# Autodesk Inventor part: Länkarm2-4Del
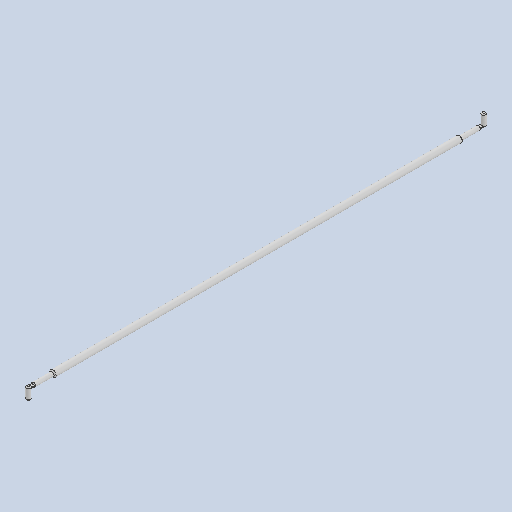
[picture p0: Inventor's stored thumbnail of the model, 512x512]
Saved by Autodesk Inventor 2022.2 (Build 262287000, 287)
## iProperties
Created: 2022-03
Part Number: Länkarm2-4Del
Material: Generic
Document SubType Name: Modeling
Designer: cl
Density: 1 g/cm^3
Appearance: Default
Author: cl
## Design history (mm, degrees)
sketch "Sketch1"
  geometry: L1 (0, 0)-(0, -2083.4); L2 (0, 0)-(-10, 0); L3 (-10, 0)-(-10, -90); L4 (-10, -90)-(-15, -90); L5 (-15, -90)-(-15, -1993.4); L6 (0, -2083.4)-(-10, -2083.4); L7 (-10, -2083.4)-(-10, -1993.4); L8 (-10, -1993.4)-(-15, -1993.4); 1 further point
  constraints: 16 end point, 5 perpendicular, 2 horizontal, 1 midpoint, 1 vertical
  dimensions: "d0" = 2083.4 distance of L1.start L1.end (computed from BladBredd); "d1" = 20 diameter of L3 L1; "d2" = 5 distance between parallel lines of L3 L5; "d3" = 90 distance of L2.end L3.end; "d4" = 20 diameter of L7 L1; "d5" = 90 vertical distance of point (-5, -2083.4) L5.end
revolve "Revolution1" sketch "Sketch1" stored, may be unused: angle "d6" = 90 deg
fillet "Fillet1" dims "d7" = 5
workplane "Work Plane1"
sketch "Sketch2"
  geometry: L1 (10, 0)-(-10, 0) reference; L2 (7.5, 0)-(-7.5, 0); L3 (-7.5, 0)-(-7.5, 20); L4 (-7.5, 20)-(7.5, 20); L5 (7.5, 20)-(7.5, 0); L6 (10, -90)-(10, 0) reference; L7 (10, -2083.4)-(-10, -2083.4) reference; L8 (7.5, -2083.4)-(-7.5, -2083.4); L9 (-7.5, -2083.4)-(-7.5, -2103.4); L10 (-7.5, -2103.4)-(7.5, -2103.4); L11 (7.5, -2103.4)-(7.5, -2083.4); 3 further points
  constraints: 16 end point, 4 parallel, 2 horizontal, 2 perpendicular, 2 point on line, 1 collinear
  dimensions: "d9" = 2.5 distance between parallel lines of L5 L6; "d10" = 15 distance of L3.end L4.end; "d11" = 20 distance of L2.end L3.end; "d12" = 20 distance of L8.end L9.end; "d13" = 15 distance of L9.end L10.end
extrude "Extrusion1" join sketch "Sketch2" distance "d14" = 4; taper "d15" = 0 deg
sketch "Sketch3"
  geometry: L1 (7.5, 20)-(-7.5, 20) reference; L2 (-7.5, -2103.4)-(7.5, -2103.4) reference; C1 r 10 at (0, 20); C2 r 10 at (0, -2103.4); 1 further point
  constraints: 2 centre point, 2 midpoint
  dimensions: "d16" = 20 diameter of C1; "d17" = 20 diameter of C2
extrude "Extrusion2" join sketch "Sketch3" distance "d18" = 8; taper "d20" = 0 deg; dims "d19" = 48, "d21" = 0
extrude "Extrusion3" join sketch "Sketch3" distance "d22" = 50; taper "d24" = 0 deg; dims "d23" = 6, "d25" = 0
fillet "Fillet2" dims "d26" = 5
body "Solid1"
other parameters: "BladBredd" = 987.5, "Fönsterhöjd" = 862, "Blad2" = 1012.5, "Blad3" = 0, "Blad4" = 0, "Blad5" = 1012.5, "Blad6" = 2025, "MGJ12Djup" = 0, "MGJ12Bredd" = 0, "MGJ2Djup" = 0, "MGJ2Bredd" = 5012.5, "MGJ56Djup" = 0, "MGJ56Bredd" = 0, "MGJ23Djup" = 48, "MGJ45Djup" = 48, "GarageRegel5" = 0, "GarageRegel6" = 0, "Styrrulle2Djup" = 0, "FönsterhöjdStyrning" = 862, "FönsterKarm" = 54, "AndraGlasraden" = 0, "BrösthöjdStyrning2" = 0.0001, "InfälldGångDörr" = 0, "Infälldstyr" = 1030.33333, "EnDelGångDörr" = 0, "VinkelJärnStyrSkena" = 1456.25, "d8" = -2
